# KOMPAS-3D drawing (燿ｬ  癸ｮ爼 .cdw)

Views: Вид 1, Спереди
Referenced files in D:\Dropbox\Copter\Frame\: Рама v2.a3d, Центр плата v.2.m3d, Полка контроллера v.2.m3d, Луч.m3d, Полка GPS v.2.m3d
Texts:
  TRAHOMOTO
  Центр плата v.2 верх
  Полка контроллера
  Луч
  Полка GPS
  Рама v2
Dimensions and other numbers on the sheet: 1:1; 1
